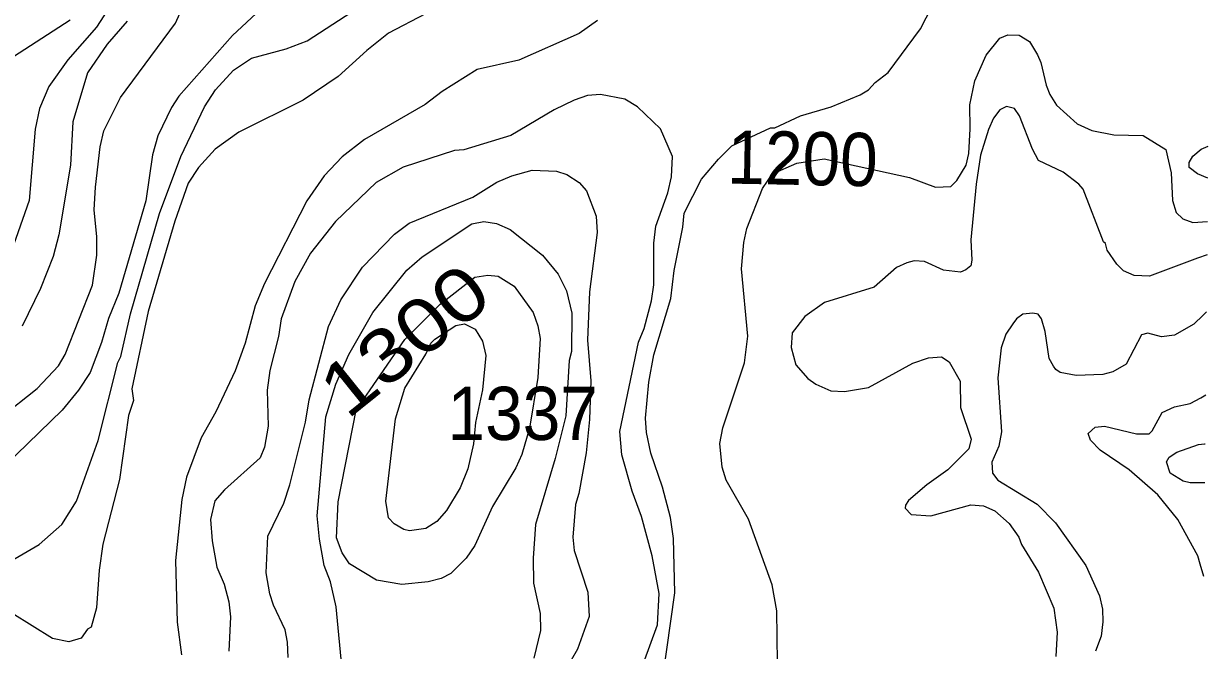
# Model space of a CAD drawing. Extents: x 598.3 to 623.2, y 6902.2 to 6930.1.
# Drawn here: x 621.169 to 622.95, y 6905.388 to 6906.33 of the extents above; entities that cross this region are included whole.
import ezdxf
from ezdxf.enums import TextEntityAlignment as Align

# ---------------------------------------------------------------- set-up
doc = ezdxf.new("R2010")
doc.units = 0
doc.header["$LTSCALE"] = 0.032
doc.layers.add('1', color=7, linetype='Continuous', lineweight=25)
doc.layers.add('2', color=7, linetype='Continuous', lineweight=13)
doc.layers.add('21', color=7, linetype='Continuous')
doc.layers.add('61', color=7, linetype='Continuous')

msp = doc.modelspace()

# ---------------------------------------------------------------- linework, layer by layer
at = {"layer": '1'}
for points in [[(621.4929, 6906.7279), (621.4469, 6906.647), (621.4224, 6906.6095), (621.3822, 6906.5337), (621.3518, 6906.4488), (621.3114, 6906.3761), (621.2786, 6906.3248), (621.2356, 6906.2754), (621.2068, 6906.2353), (621.1928, 6906.2022), (621.1865, 6906.1712), (621.1772, 6906.0639), (621.1473, 6905.9784)], [(621.7731, 6906.3446), (621.7174, 6906.3158), (621.6847, 6906.2897), (621.6416, 6906.2505), (621.589, 6906.2151), (621.4924, 6906.1669), (621.457, 6906.1414), (621.4318, 6906.1138), (621.4163, 6906.0901), (621.3965, 6906.0331), (621.3562, 6905.8974), (621.3319, 6905.7809), (621.3341, 6905.7636), (621.3268, 6905.741), (621.3131, 6905.6446), (621.2881, 6905.5474), (621.2824, 6905.5086)], [(622.3023, 6905.369), (622.3015, 6905.4473), (622.2941, 6905.4862), (622.2585, 6905.585), (622.2253, 6905.6436), (622.2189, 6905.6631), (622.2157, 6905.6989), (622.2199, 6905.7226), (622.2528, 6905.8203), (622.2578, 6905.8602), (622.2482, 6905.9612), (622.2515, 6906.001), (622.2563, 6906.0221), (622.2796, 6906.0822), (622.295, 6906.1044), (622.3313, 6906.1202), (622.3724, 6906.1268), (622.5005, 6906.0989), (622.5396, 6906.0842), (622.5628, 6906.085), (622.5721, 6906.0941), (622.5861, 6906.1173), (622.5897, 6906.1349), (622.5921, 6906.172), (622.5913, 6906.2077), (622.5987, 6906.2439), (622.6158, 6906.2827), (622.6363, 6906.3079), (622.6483, 6906.3132), (622.6655, 6906.3124), (622.6813, 6906.3033), (622.693, 6906.2831), (622.6983, 6906.2714), (622.706, 6906.2376), (622.7115, 6906.2236), (622.7217, 6906.2075), (622.7527, 6906.1793), (622.7746, 6906.1691), (622.8077, 6906.163), (622.8518, 6906.1618), (622.8859, 6906.1407), (622.8942, 6906.1057), (622.896, 6906.064), (622.9015, 6906.0459), (622.9117, 6906.0364), (622.9267, 6906.0309), (622.9488, 6906.0325)], [(621.2824, 6905.5086), (621.2786, 6905.4517), (621.2704, 6905.4225), (621.2651, 6905.4198), (621.2554, 6905.4064), (621.2371, 6905.4005), (621.2126, 6905.4059), (621.1512, 6905.4438)]]:
    msp.add_lwpolyline(points, dxfattribs=at)
msp.add_lwpolyline([(621.6417, 6905.6112), (621.6691, 6905.7488), (621.7422, 6905.8549), (621.7954, 6905.9081), (621.8472, 6905.9487), (621.867, 6905.952), (621.8822, 6905.9505), (621.9063, 6905.9354), (621.9349, 6905.8955), (621.9422, 6905.8758), (621.9454, 6905.8566), (621.9421, 6905.7981), (621.9295, 6905.7221), (621.9181, 6905.6825), (621.909, 6905.6624), (621.874, 6905.6039), (621.8473, 6905.5456), (621.8343, 6905.5262), (621.8112, 6905.5034), (621.7967, 6905.4958), (621.777, 6905.4907), (621.7375, 6905.4868), (621.6993, 6905.4933), (621.6588, 6905.5179), (621.6477, 6905.5343), (621.6395, 6905.5572)], close=True, dxfattribs=at)
at = {"layer": '2'}
for points in [[(621.1332, 6905.7376), (621.1895, 6905.7815), (621.2213, 6905.8158), (621.2316, 6905.8327), (621.2725, 6905.9367), (621.2793, 6905.9819), (621.2792, 6906.0094), (621.2752, 6906.05), (621.2768, 6906.0842), (621.284, 6906.1448), (621.2897, 6906.1688), (621.3147, 6906.2191), (621.3972, 6906.3308), (621.4124, 6906.3643), (621.4474, 6906.4279), (621.4892, 6906.4746), (621.5209, 6906.5014), (621.5488, 6906.5206), (621.5744, 6906.5453), (621.6282, 6906.6081), (621.6617, 6906.6398), (621.6872, 6906.6568)], [(621.8113, 6906.5699), (621.7598, 6906.5549), (621.7153, 6906.5324), (621.6924, 6906.5158), (621.627, 6906.4328), (621.5846, 6906.396), (621.5683, 6906.3917), (621.4829, 6906.3119), (621.4024, 6906.2209), (621.3912, 6906.2037), (621.3709, 6906.1611), (621.3626, 6906.1325), (621.3528, 6906.0637), (621.3123, 6905.9246), (621.2966, 6905.8868), (621.2862, 6905.8508), (621.2689, 6905.8055), (621.2516, 6905.7788), (621.2269, 6905.7487), (621.1064, 6905.6323)], [(621.1502, 6905.5222), (621.1922, 6905.5471), (621.2262, 6905.5769), (621.2483, 6905.612), (621.2809, 6905.7031), (621.3106, 6905.8205), (621.3149, 6905.8294), (621.3297, 6905.8937), (621.3732, 6906.0447), (621.4053, 6906.1301), (621.4411, 6906.2047), (621.4574, 6906.2303), (621.4845, 6906.2601), (621.5118, 6906.2782), (621.5636, 6906.2922), (621.5952, 6906.3041), (621.7282, 6906.3908)], [(622.1299, 6905.3465), (622.1477, 6905.4741), (622.1461, 6905.5558), (622.1414, 6905.5877), (622.1292, 6905.633), (622.1118, 6905.6845), (622.1052, 6905.7155), (622.104, 6905.7368), (622.109, 6905.7911), (622.1162, 6905.8322), (622.1421, 6905.9166), (622.147, 6905.9591), (622.16, 6906.024), (622.162, 6906.045), (622.1879, 6906.0959), (622.2135, 6906.1264), (622.2336, 6906.1463), (622.2919, 6906.1731), (622.2983, 6906.1732), (622.3369, 6906.1911), (622.3832, 6906.2047), (622.4267, 6906.2228), (622.439, 6906.2305), (622.4493, 6906.2415), (622.4688, 6906.2563), (622.5173, 6906.3222), (622.5342, 6906.355)], [(621.1539, 6906.2805), (621.2392, 6906.3357)], [(622.0318, 6906.3349), (622.004, 6906.3153), (621.9133, 6906.2752), (621.851, 6906.2612), (621.798, 6906.228), (621.7727, 6906.2082), (621.6813, 6906.156), (621.6479, 6906.1298), (621.6208, 6906.1011), (621.5948, 6906.0637), (621.531, 6905.9395), (621.5172, 6905.9055), (621.5021, 6905.8495), (621.4871, 6905.808), (621.458, 6905.7463), (621.436, 6905.7072), (621.4136, 6905.6482), (621.407, 6905.6145), (621.3973, 6905.5228), (621.3999, 6905.43), (621.4063, 6905.3813)], [(621.3247, 6906.3334), (621.2945, 6906.2989), (621.2651, 6906.2558), (621.2428, 6906.1824), (621.2395, 6906.1173), (621.2218, 6906.0124), (621.2136, 6905.9797), (621.1944, 6905.9317), (621.1669, 6905.875)], [(622.1006, 6905.3688), (622.1218, 6905.4264), (622.1243, 6905.4735), (622.1137, 6905.5299), (622.0976, 6905.5893), (622.084, 6905.6271), (622.0684, 6905.6818), (622.0653, 6905.7168), (622.0933, 6905.8509), (622.1018, 6905.8718), (622.1129, 6905.9133), (622.1162, 6905.9371), (622.1163, 6906.0001), (622.1192, 6906.0257), (622.1373, 6906.0755), (622.143, 6906.0998), (622.1445, 6906.1302), (622.1262, 6906.1718), (622.0917, 6906.2049), (622.0729, 6906.2162), (622.0364, 6906.2233), (622.0169, 6906.2218), (621.9967, 6906.215), (621.9664, 6906.2006), (621.9015, 6906.1618), (621.8307, 6906.14), (621.8167, 6906.1391), (621.7398, 6906.114), (621.6988, 6906.0912), (621.6378, 6906.0323), (621.6005, 6905.9851), (621.5769, 6905.9423), (621.5561, 6905.8861), (621.5519, 6905.8597), (621.5391, 6905.8086), (621.535, 6905.7792), (621.5366, 6905.725), (621.531, 6905.6934), (621.5246, 6905.6773), (621.4712, 6905.6294), (621.4566, 6905.6124), (621.45, 6905.5846), (621.4524, 6905.5523), (621.4595, 6905.5127), (621.4703, 6905.4873), (621.4774, 6905.4606), (621.48, 6905.4384), (621.4774, 6905.3869)], [(622.9483, 6905.9826), (622.9337, 6905.9772), (622.8615, 6905.9505), (622.8383, 6905.9511), (622.8226, 6905.9583), (622.8124, 6905.9684), (622.7979, 6905.9892), (622.7956, 6905.9993), (622.7921, 6906.0018), (622.7616, 6906.0809), (622.7554, 6906.0885), (622.7316, 6906.1066), (622.6947, 6906.1242), (622.6855, 6906.141), (622.6661, 6906.1913), (622.6584, 6906.2022), (622.6464, 6906.2055), (622.6364, 6906.2004), (622.6271, 6906.1876), (622.6193, 6906.171), (622.6076, 6906.1322), (622.6011, 6906.0888), (622.593, 6906.0049), (622.5943, 6905.9743), (622.5931, 6905.966), (622.5856, 6905.9597), (622.5773, 6905.9564), (622.552, 6905.9596), (622.5231, 6905.9724), (622.5077, 6905.9735), (622.4966, 6905.9706), (622.4811, 6905.9634), (622.4477, 6905.9339), (622.3727, 6905.9107), (622.3436, 6905.8898), (622.3243, 6905.8652), (622.3227, 6905.8432), (622.3297, 6905.8171), (622.3478, 6905.7965), (622.3598, 6905.7882), (622.3823, 6905.7782), (622.4032, 6905.7769), (622.439, 6905.783), (622.5056, 6905.8194), (622.5293, 6905.8274), (622.549, 6905.8291), (622.5604, 6905.8214), (622.5768, 6905.7924), (622.5776, 6905.753), (622.5936, 6905.7055), (622.5898, 6905.691), (622.5584, 6905.6593), (622.5268, 6905.6366), (622.4993, 6905.6131), (622.4946, 6905.6062), (622.4943, 6905.6017), (622.5034, 6905.592), (622.5327, 6905.5903), (622.5928, 6905.6064), (622.6119, 6905.605), (622.6289, 6905.5975), (622.6503, 6905.5785), (622.6649, 6905.5581), (622.6693, 6905.5469), (622.6948, 6905.5056), (622.7178, 6905.4514), (622.7225, 6905.4153), (622.7209, 6905.3788)], [(622.9494, 6906.0978), (622.9337, 6906.1041), (622.9212, 6906.1135), (622.9212, 6906.1214), (622.9267, 6906.1308), (622.9392, 6906.1411), (622.9499, 6906.1458)], [(621.5665, 6905.3769), (621.5659, 6905.4003), (621.5624, 6905.4185), (621.5447, 6905.4557), (621.5391, 6905.4727), (621.5334, 6905.5044), (621.5359, 6905.5596), (621.5603, 6905.6089), (621.5694, 6905.6369), (621.5927, 6905.731), (621.5982, 6905.7647), (621.6273, 6905.8748), (621.6458, 6905.9147), (621.6784, 6905.9637), (621.7264, 6906.0133), (621.7485, 6906.0298), (621.8445, 6906.0693), (621.8806, 6906.0918), (621.903, 6906.1012), (621.9335, 6906.1099), (621.97, 6906.1084), (621.9854, 6906.103), (622.0042, 6906.091), (622.015, 6906.0785), (622.0297, 6906.0407), (622.0312, 6906.0159), (622.0199, 6905.9269), (622.0167, 6905.8543), (622.0215, 6905.7931), (622.0198, 6905.7347), (622.0145, 6905.6849), (622.0037, 6905.6236), (621.9988, 6905.6073), (621.9948, 6905.5581), (621.9968, 6905.5379), (622.0173, 6905.4752), (622.0192, 6905.4388), (622.0018, 6905.3899), (621.9749, 6905.3437)], [(621.6483, 6905.3534), (621.6387, 6905.4533), (621.6305, 6905.4911), (621.6208, 6905.5153), (621.6136, 6905.555), (621.6103, 6905.5902), (621.6233, 6905.739), (621.6385, 6905.7881), (621.658, 6905.8324), (621.6942, 6905.8959), (621.7453, 6905.9592), (621.7679, 6905.9796), (621.8426, 6906.029), (621.861, 6906.0323), (621.8798, 6906.0293), (621.9005, 6906.0207), (621.949, 6905.9818), (621.9728, 6905.9531), (621.9852, 6905.9282), (621.9931, 6905.8945), (621.9924, 6905.8373), (621.9892, 6905.8235), (621.9842, 6905.7402), (621.9683, 6905.6761), (621.9385, 6905.5769), (621.9348, 6905.5263), (621.9357, 6905.4889), (621.9455, 6905.4433), (621.9462, 6905.4177), (621.9359, 6905.3763)], [(622.9474, 6905.8965), (622.942, 6905.8915), (622.9279, 6905.8784), (622.8991, 6905.8619), (622.8793, 6905.8591), (622.8588, 6905.8646), (622.8495, 6905.8621), (622.8264, 6905.8182), (622.8063, 6905.8067), (622.7912, 6905.8023), (622.7514, 6905.8009), (622.7274, 6905.8057), (622.7205, 6905.8102), (622.7173, 6905.8152), (622.7109, 6905.8267), (622.7045, 6905.8674), (622.6991, 6905.8863), (622.694, 6905.893), (622.686, 6905.8948), (622.671, 6905.8931), (622.6615, 6905.8862), (622.656, 6905.8786), (622.6455, 6905.863), (622.6384, 6905.8424), (622.6335, 6905.7973), (622.6392, 6905.7161), (622.6351, 6905.695), (622.6246, 6905.6709), (622.6253, 6905.6541), (622.6336, 6905.6436), (622.6926, 6905.6074), (622.7203, 6905.5796), (622.7656, 6905.5156), (622.7864, 6905.4697), (622.7906, 6905.4498), (622.7913, 6905.4307), (622.7887, 6905.4093), (622.7805, 6905.3866)], [(622.9433, 6905.4987), (622.9379, 6905.5176), (622.9344, 6905.5299), (622.904, 6905.5844), (622.8739, 6905.6216), (622.831, 6905.6591), (622.7875, 6905.689), (622.773, 6905.7036), (622.7694, 6905.7136), (622.7797, 6905.7233), (622.7938, 6905.7248), (622.8418, 6905.7134), (622.8609, 6905.7132), (622.8657, 6905.718), (622.8803, 6905.7455), (622.8992, 6905.7539), (622.9224, 6905.7587), (622.9387, 6905.7677), (622.9461, 6905.7718)], [(622.9447, 6905.6399), (622.9392, 6905.6399), (622.9225, 6905.6398), (622.912, 6905.6422), (622.8927, 6905.6542), (622.8869, 6905.6713), (622.8911, 6905.6785), (622.9027, 6905.686), (622.9354, 6905.6972), (622.9444, 6905.6981), (622.9453, 6905.6982)]]:
    msp.add_lwpolyline(points, dxfattribs=at)
msp.add_lwpolyline([(621.7136, 6905.6119), (621.7281, 6905.7357), (621.7421, 6905.782), (621.7737, 6905.833), (621.781, 6905.8498), (621.7874, 6905.8557), (621.8187, 6905.876), (621.8318, 6905.8787), (621.8478, 6905.8708), (621.8588, 6905.8524), (621.8636, 6905.8313), (621.8588, 6905.7795), (621.8482, 6905.7302), (621.8451, 6905.6983), (621.837, 6905.6605), (621.825, 6905.632), (621.8049, 6905.5981), (621.7902, 6905.5816), (621.7736, 6905.5709), (621.7491, 6905.5677), (621.7406, 6905.5696), (621.726, 6905.5781), (621.7173, 6905.5871)], close=True, dxfattribs=at)

# ---------------------------------------------------------------- texts
at = {"layer": '21', "width": 0.95}
msp.add_text('1337', height=0.08, dxfattribs=at).set_placement((621.8062, 6905.7041))
at = {"layer": '61'}
for s, rotation, width, p in [('1200', 358.898, 0.95, (622.3392, 6906.0874)), ('1300', 38.82, 1.2, (621.7665, 6905.8231))]:
    msp.add_text(s, height=0.08, rotation=rotation, dxfattribs=dict(at, width=width)).set_placement(p, align=Align.CENTER)

doc.saveas('drawing.dxf')
